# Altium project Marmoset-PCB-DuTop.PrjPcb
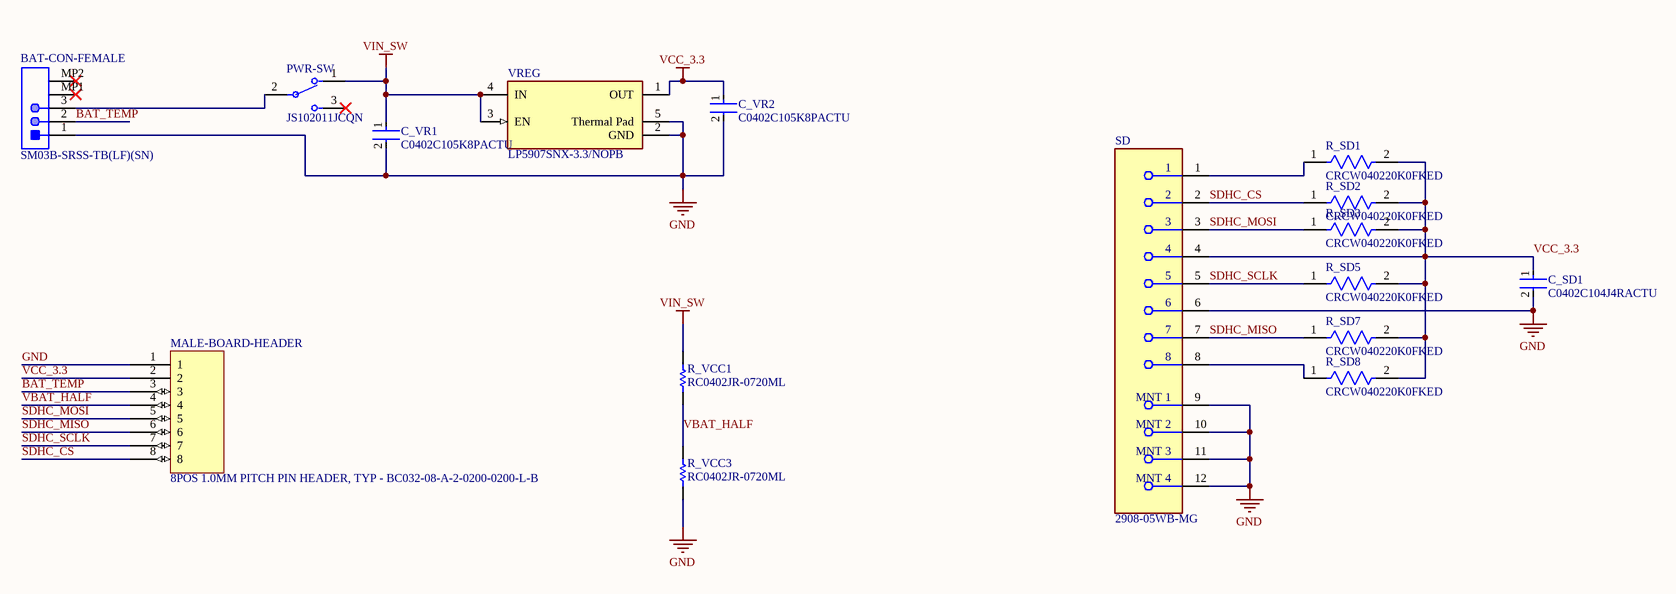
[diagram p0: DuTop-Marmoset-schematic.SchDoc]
1 sheet, 16 parts. Net scope: global (net labels, ports and power ports of the same name join across sheets).
Board file: DuTop-Marmoset-PCB1.PcbDoc

## Sheet DuTop-Marmoset-schematic.SchDoc
size A3; SheetNumber: 1; SheetTotal: 1

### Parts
BAT-CON-FEMALE  SM03B-SRSS-TB(LF)(SN)  [JST-SM03B-SRSS-TB_V]
C_SD1  C0402C104J4RACTU  [FP-C0402-BB-MFG]
C_VR1  C0402C105K8PACTU  [FP-C0402C105K8PACTU-MFG]
C_VR2  C0402C105K8PACTU  [FP-C0402C105K8PACTU-MFG]
MALE-BOARD-HEADER  8POS 1.0MM PITCH PIN HEADER, TYP - BC032-08-A-2-0200-0200-L-B  [MALE-BOARD-HEADER-8]
PWR-SW  JS102011JCQN  [FP-JS102011JCQN-MFG]
R_SD1  CRCW040220K0FKED  [FP-CRCW0402-e3-IPC_B]
R_SD2  CRCW040220K0FKED  [FP-CRCW0402-e3-IPC_B]
R_SD3  CRCW040220K0FKED  [FP-CRCW0402-e3-IPC_B]
R_SD5  CRCW040220K0FKED  [FP-CRCW0402-e3-IPC_B]
R_SD7  CRCW040220K0FKED  [FP-CRCW0402-e3-IPC_B]
R_SD8  CRCW040220K0FKED  [FP-CRCW0402-e3-IPC_B]
R_VCC1  RC0402JR-0720ML  [RESC1005X40X25NL05T10]
R_VCC3  RC0402JR-0720ML  [RESC1005X40X25NL05T10]
SD  2908-05WB-MG  [FP-2908-05WB-MG-MFG]
VREG  LP5907SNX-3.3/NOPB  [FP-DQN0004A-MFG]

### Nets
GND: BAT-CON-FEMALE.1 C_SD1.2 C_VR1.2 C_VR2.2 MALE-BOARD-HEADER.1 R_VCC3.1 SD.6 SD.9(MNT_1) SD.10(MNT_2) SD.11(MNT_3) SD.12(MNT_4) VREG.2(GND) VREG.5(Thermal_Pad)
VCC_3.3: C_SD1.1 C_VR2.1 MALE-BOARD-HEADER.2 R_SD1.2 R_SD2.2 R_SD3.2 R_SD5.2 R_SD7.2 R_SD8.2 SD.4 VREG.1(OUT)
VIN_SW: C_VR1.1 PWR-SW.1 R_VCC1.2 VREG.3(EN) VREG.4(IN)
BAT_TEMP: BAT-CON-FEMALE.2 MALE-BOARD-HEADER.3
SDHC_CS: MALE-BOARD-HEADER.8 R_SD2.1 SD.2
SDHC_MISO: MALE-BOARD-HEADER.6 R_SD7.1 SD.7
SDHC_MOSI: MALE-BOARD-HEADER.5 R_SD3.1 SD.3
SDHC_SCLK: MALE-BOARD-HEADER.7 R_SD5.1 SD.5
VBAT_HALF: MALE-BOARD-HEADER.4 R_VCC1.1 R_VCC3.2
NetBAT-CON-FEMALE_3: BAT-CON-FEMALE.3 PWR-SW.2
NetR_SD1_1: R_SD1.1 SD.1
NetR_SD8_1: R_SD8.1 SD.8

Not connected (* = marked no-connect by the designer): BAT-CON-FEMALE MP1* MP2*; PWR-SW 3*

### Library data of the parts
BAT-CON-FEMALE = CMP-2000-07077-1: Male Header, Pitch 1 mm, 1 x 3 Position, Height 2.9 mm, -25 to 85 degC, RoHS, Tape and Reel; Manufacturer: JST; Pitch: 1mm; Style/Orientation: RightAngleHeader/Plug; No of Positions: 3
C_SD1 = CMP-1034-02068-3: CAP CER 0.1UF 16V 5% X7R 0402; Manufacturer: Kemet; Value: 0.10 μF; Temperature Coefficient: 15%; Tolerance: 0.05
C_VR1 C_VR2 = CMP-2008-02081-2: CAP CER 1UF 10V X5R 0402; Dielectric Material: Ceramic; Dissipation Factor: 5%; Tolerance: 10%
MALE-BOARD-HEADER = MALE-BOARD-HEADER-8P: System: Connector
PWR-SW = CMP-10038-000010-1: SWITCH SLIDE SPDT 300MA 6V; Electrical Life: 5000Cycles; Switch Function: On-On; Actuator Material: Nylon; Actuator Length: 2mm; Actuator Type: Standard
R_SD1-R_SD3 R_SD5 R_SD7 R_SD8 = CMP-2002-08356-2: RES Thick Film, 20kΩ, 1%, 0.063W, 100ppm/°C, 0402; Max Power Dissipation: 63mW; Working Voltage: 50V; Resistance: 20kR
R_VCC1 R_VCC3 = CMP-2002-06961-1: Manufacturer: Yageo
SD = CMP-2000-05030-2: CONN MICRO SD CARD PUSH-PUSH R/A; Gender: Male; Number of Positions: 8; Connector Type: Connector; Pitch: 1.1mm; Body Material: Thermoplastic; Current Rating: 500mA
VREG = CMP-04917-000059-2: None; Number of Regulators: 1; Min Input Voltage: 2.2V; Quiescent Current: 250uA; Max Input Voltage: 5.5V; Power Supply Rejection Ratio (PSRR): 82dB; Max Output Current: 250mA; Accuracy: 2%; Polarity: Positive; Output Voltage: 3.3V; Output Type: Fixed; Dropout Voltage: 250mV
